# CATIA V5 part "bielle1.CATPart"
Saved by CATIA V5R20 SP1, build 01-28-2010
Part number: Part1.1
Bounding box of the stored display mesh (mm): x 48 to 87, y 0 to 5, z 28.093 to 41.907
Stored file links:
  E:\EDELI\gcausse\Edeli_2012_685_gcausse\bielle1.CATPart
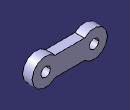
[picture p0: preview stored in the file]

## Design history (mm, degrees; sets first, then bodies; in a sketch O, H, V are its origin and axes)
Parameters
  long = 0.025
  diamtrou = 0.005
Body1 (main body)
  Sketch1 on zx-plane, origin (0, 0, 0), H (-1, 0, 0), V (0, 0, 1)
    line L1 (-59.899, 40) -> (-75.101, 40)
    line L2 (-59.899, 30) -> (-75.101, 30)
    arc A1 centre (-55, 35) radius 7 from (-59.899, 40) to (-59.899, 30) cw
    point P5 (-55, 35)
    point P6 (-50.101, 30)
    arc A2 centre (-80, 35) radius 7 from (-75.101, 40) to (-75.101, 30) ccw
    point P7 (-80, 35)
    circle A3 centre (-55, 35) radius 2.5
    distance P7 L1 = 5
    distance P5 L2 = 5
    distance L2 L1 = 10
    radius A1 = 7
    radius A2 = 7
    distance P5 P7 = 25 {= long}
    radius A3 = 2.5
    horizontal: L1 H, L2 H
    coincidence: A1 P6, P6 L2
  Pad1: profile Sketch1, direction (0, 1, 0), length 5
  Sketch2 on end face of Pad1, origin (0, 5, 0), H (-1, 0, 0), V (0, 0, 1)
    circle A1 centre (-80, 35) radius 2.5
    reference projected arc E1 centre (-80, 35) radius 7 from (-75.101, 40) to (-75.101, 30) ccw from edge [face of Pad1 from Sketch1.A2 | end face of Pad1]
    reference projected arc E2 centre (-80, 35) radius 7 from (-75.101, 40) to (-75.101, 30) ccw from edge [face of Pad1 from Sketch1.A2 | end face of Pad1]
    radius A1 = 2.5
    radius E2 = 7 (reference)
    concentricity: A1 E1
  Pocket1: profile Sketch2, direction (0, -1, 0), length 5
